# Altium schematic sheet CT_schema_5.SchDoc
size 259 x 245 mm
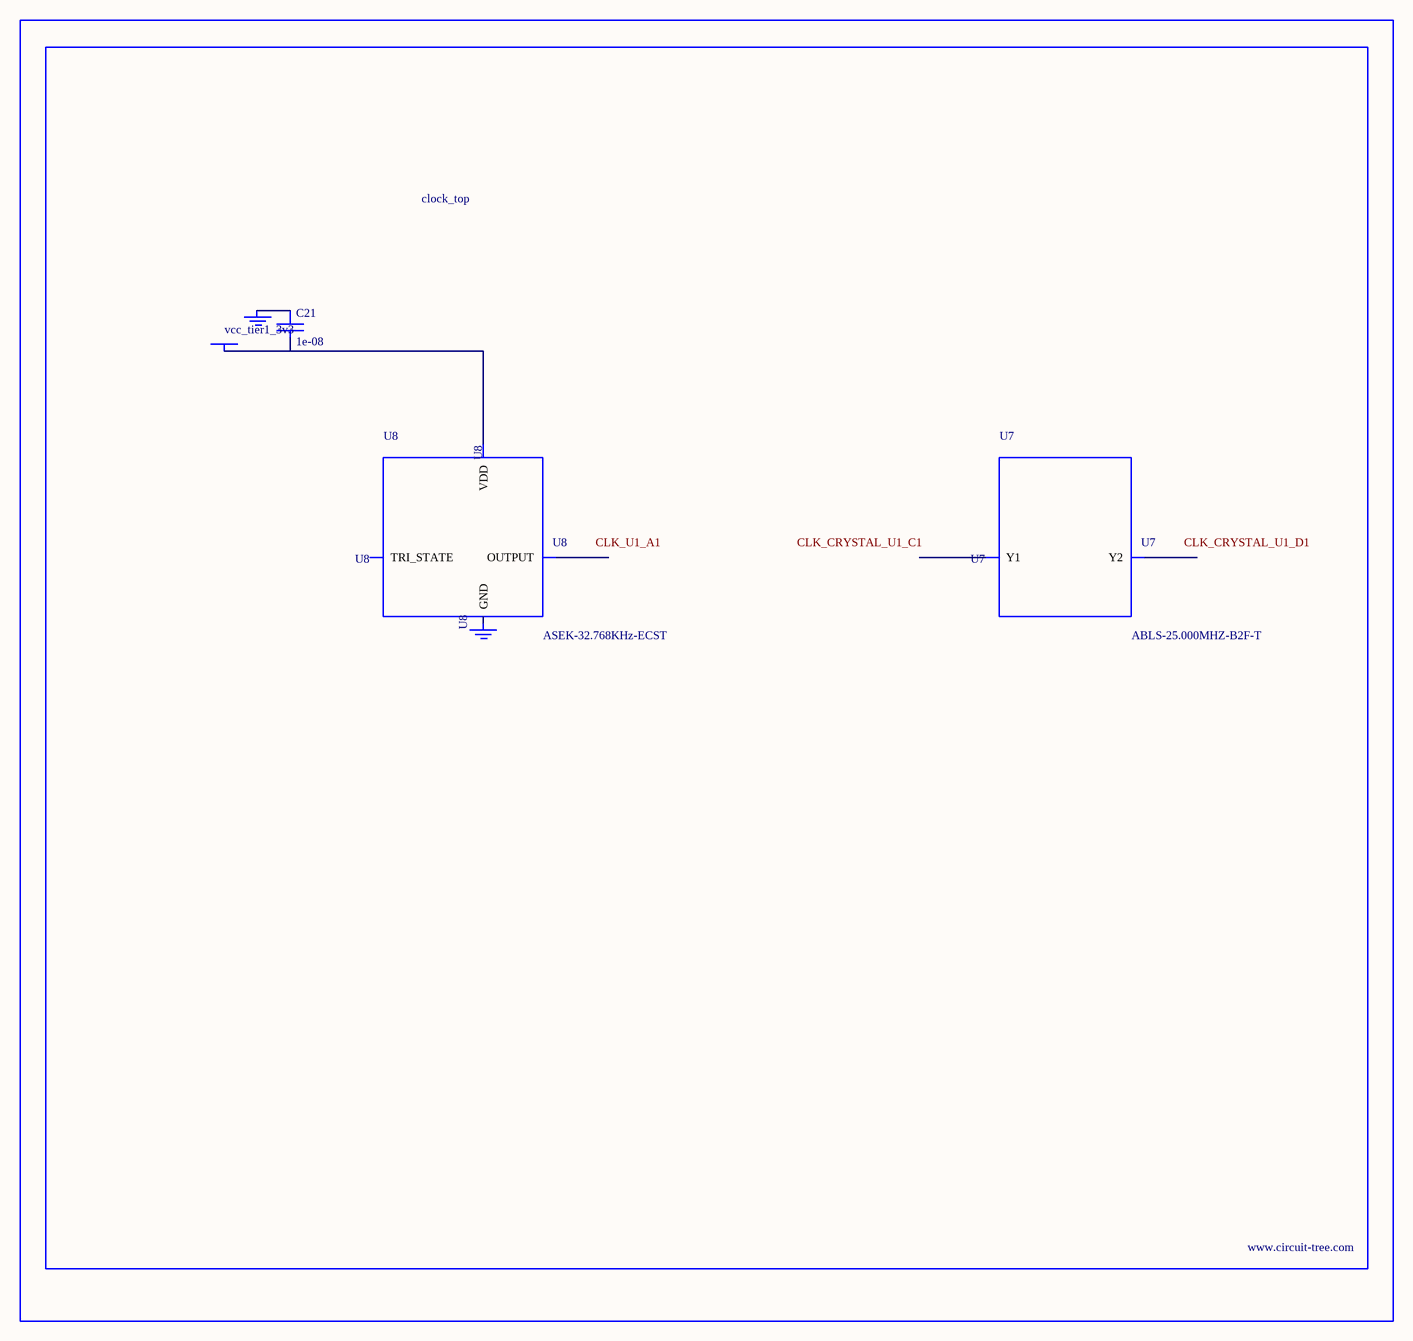
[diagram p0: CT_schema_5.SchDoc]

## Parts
BORDER4  (no value)
C21  1e-08  [C0402]
GND_INSTANCE_4_0  (no value)
GND_INSTANCE_4_1  (no value)
POWER_INSTANCE_4_0  vcc_tier1_3v3
U7  ABLS-25.000MHZ-B2F-T  [ABLS-25.000MHZ-B2F-T]
U8  ASEK-32.768KHz-ECST  [ASEK]

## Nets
NetC21_1: C21.1 GND_INSTANCE_4_0.0(GND)
NetC21_2: C21.2 POWER_INSTANCE_4_0.0(PWR) U8.4(VDD)

Not connected (* = marked no-connect by the designer): GND_INSTANCE_4_1 0(GND); U7 1(Y1) 2(Y2); U8 1(TRI_STATE) 2(GND) 3(OUTPUT)

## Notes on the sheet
- Labels drawn without touching a wire or pin: CLK_CRYSTAL_U1_C1, CLK_CRYSTAL_U1_D1, CLK_U1_A1

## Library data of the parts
BORDER4 = BORDER_PAGE4
C21 = C0402C103K3RAC
GND_INSTANCE_4_0 GND_INSTANCE_4_1 = GND
POWER_INSTANCE_4_0 = PWR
